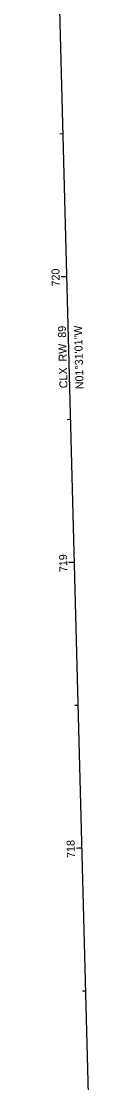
# Model space of a CAD drawing. Extents: x 2045805 to 2050091, y 455249 to 458900.
# Drawn here: x 2047587.3 to 2047613.4, y 458151.9 to 458523.3 of the extents above; entities that cross this region are included whole.
import ezdxf

# ---------------------------------------------------------------- set-up
doc = ezdxf.new("R2010")
doc.units = 0
for name, color, linetype in [('GE_P_Alignment_100_Cardinal_Points', 7, 'Continuous'), ('GE_P_Alignment_100_Curve_Data', 7, 'Continuous'), ('GE_P_Alignment_100_Stations', 7, 'Continuous'), ('GE_P_Driveway_CL', 7, 'Continuous'), ('PF_X_Ground_Line', 7, 'Continuous'), ('PV_P_EOP', 7, 'Continuous'), ('PV_X_EOP', 7, 'Continuous'), ('RW_X_CL_100_Stations', 7, 'Continuous'), ('SC_Scratch1', 7, 'Continuous'), ('SC_Scratch3', 7, 'Continuous')]:
    doc.layers.add(name, color=color, linetype=linetype)

msp = doc.modelspace()

# ---------------------------------------------------------------- linework, layer by layer
at = {"layer": 'GE_P_Alignment_100_Cardinal_Points'}
for p, q in [((2047598.3, 458483.91), (2047597.1, 458483.88)), ((2047599.62, 458433.93), (2047597.62, 458433.87)), ((2047600.95, 458383.95), (2047599.75, 458383.91)), ((2047602.27, 458333.96), (2047600.27, 458333.91)), ((2047603.59, 458283.98), (2047602.39, 458283.95)), ((2047604.92, 458234), (2047602.92, 458233.94)), ((2047606.24, 458184.02), (2047605.04, 458183.98))]:
    msp.add_line(p, q, dxfattribs=at)
at = {"layer": 'GE_P_Alignment_100_Stations'}
for p, q in [((2047599.62, 458433.93), (2047597.62, 458433.87)), ((2047602.27, 458333.96), (2047601.07, 458333.93)), ((2047604.92, 458234), (2047603.72, 458233.97))]:
    msp.add_line(p, q, dxfattribs=at)
at = {"layer": 'PV_P_EOP'}
msp.add_line((2047613.37, 457914.72), (2047587.33, 458898), dxfattribs=at)
at = {"layer": 'PV_X_EOP'}
msp.add_line((2047599.62, 458433.93), (2047597.62, 458433.87), dxfattribs=at)

# ---------------------------------------------------------------- texts
at = {"layer": 'GE_P_Alignment_100_Cardinal_Points'}
for s, p in [('720', (2047597.16, 458430.58)), ('719', (2047599.81, 458330.64)), ('718', (2047602.46, 458230.65))]:
    msp.add_text(s, height=2.8, rotation=91.5169, dxfattribs=at).set_placement(p)
at = {"layer": 'GE_P_Alignment_100_Curve_Data'}
msp.add_text('N01°31\'01"W', height=2.8, rotation=91.5169, dxfattribs=at).set_placement((2047605.47, 458394.63))
at = {"layer": 'GE_P_Alignment_100_Stations'}
msp.add_text('720', height=2.8, rotation=91.5169, dxfattribs=at).set_placement((2047597.16, 458430.58))
at = {"layer": 'GE_P_Driveway_CL'}
msp.add_text('CLX_RW_89', height=2.8, rotation=91.5169, dxfattribs=at).set_placement((2047599.83, 458394.97))
at = {"layer": 'PF_X_Ground_Line'}
msp.add_text('N01°31\'01"W', height=2.8, rotation=91.5169, dxfattribs=at).set_placement((2047605.47, 458394.63))
at = {"layer": 'PV_X_EOP'}
msp.add_text('720', height=2.8, rotation=91.5169, dxfattribs=at).set_placement((2047597.16, 458430.58))
at = {"layer": 'RW_X_CL_100_Stations'}
msp.add_text('CLX_RW_89', height=2.8, rotation=91.5169, dxfattribs=at).set_placement((2047599.83, 458394.97))
at = {"layer": 'SC_Scratch1'}
msp.add_text('N01°31\'01"W', height=2.8, rotation=91.5169, dxfattribs=at).set_placement((2047605.47, 458394.63))
at = {"layer": 'SC_Scratch3'}
msp.add_text('CLX_RW_89', height=2.8, rotation=91.5169, dxfattribs=at).set_placement((2047599.83, 458394.97))

doc.saveas('drawing.dxf')
